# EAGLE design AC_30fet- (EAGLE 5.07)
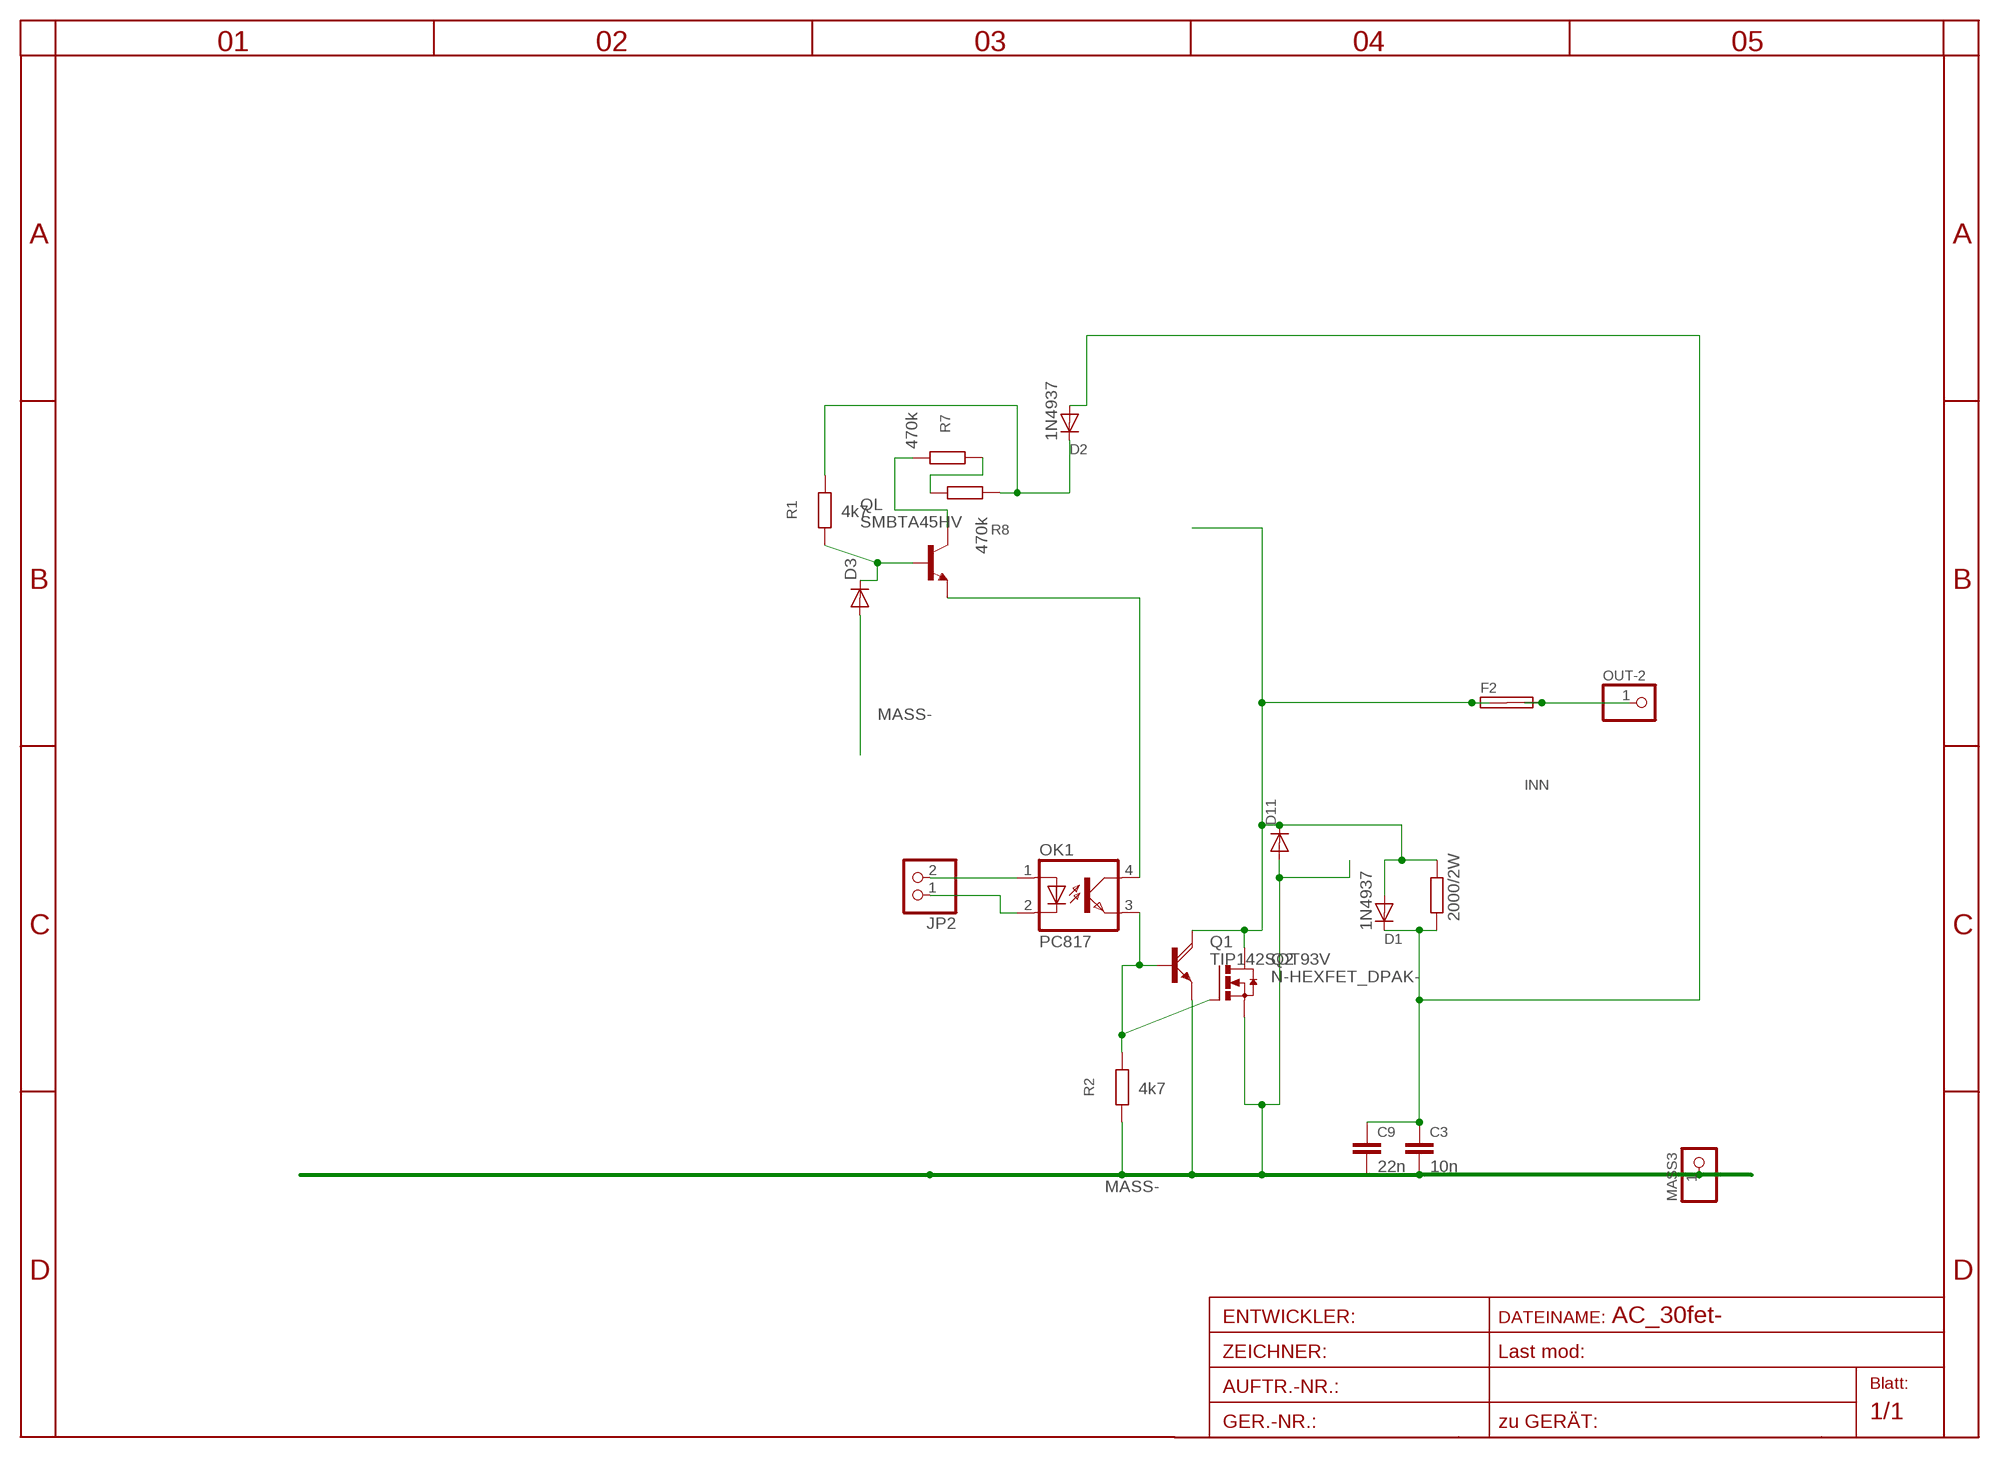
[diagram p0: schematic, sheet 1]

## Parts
C3  10n  C-EU025_050-050X075  [C025_050-050X075]
C9  22n  C-EU150-054X183  [C150-054X183]
D1  1N4937  1N4004DO41-10  [DO41-10]
D2  1N4937  1N400420  [DO41-20]
D3  DIODE-MINIMELF  [MINIMELF]
D11  DIODE-SMC  [SMC]
F2  SHK20L7MM5  [7MM5]
JP2  PINHD-1X2STR  [1X02]
MASS3  PINHD-1X13MM2  [1X3MM2]
OK1  PC817  [DIL04]
OUT-2  PINHD-1X13MM2  [1X3MM2]
Q1  TIP142SOT93V  [SOT93V]
Q2  N-HEXFET_DPAK-  [TO252]
QL  SMBTA45HV  [SOT23HV]
R1  4k7  R-EU_R1206  [R1206]
R2  4k7  R-EU_R1206  [R1206]
R7  470k  R-EU_R1206  [R1206]
R8  470k  R-EU_R1206  [R1206]
R27  2000/2W  R-EU_0207/10  [0207/10]

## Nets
BQL: D3.C QL.1(B) R1.2
D1: D1.A D11.C F2.1A F2.1B Q1.C Q2.3(D) R27.2
INN: F2.2A F2.2B OUT-2.1
MASS-: C3.3 C9.2 D3.A D11.A MASS3.1 Q1.E Q2.2(S) R2.2
N$1: R7.1 R8.2
N$2: C3.1 C9.1 D1.C D2.A R27.1
N$3: JP2.1 OK1.2(C)
N$4: OK1.3(EMIT) Q1.B Q2.1(G) R2.1
N$6: D2.C R1.1 R8.1
N$7: JP2.2 OK1.1(A)
N$9: QL.3(C) R7.2
N$11: OK1.4(COL) QL.2(E)

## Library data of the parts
C3 C9 = rcl-2:C-EU: CAPACITOR, European symbol
D1 D2 = diode:1N4004: DIODE
D3 D11 = diode:DIODE-: DIODE
F2 = fuse:SHK20L: FUSE HOLDER 5 x 20 mm, SH contact, SHH1 Schukat, E1073 Buerklin
JP2 = pinhead:PINHD-1X2: PIN HEADER
MASS3 OUT-2 = pinhead:PINHD-1X1: PIN HEADER
OK1 = optocoupler:PC817: SHARP OPTO COUPLER
Q1 = transistor-power:TIP142: NPN DARLINGTON TRANSISTOR
Q2 = transistor-power:N-HEXFET_?-*: HEXFET® Power MOSFET
QL = transistor-npn:SMBTA45
R1 R2 R7 R8 R27 = rcl-2:R-EU_: RESISTOR, European symbol

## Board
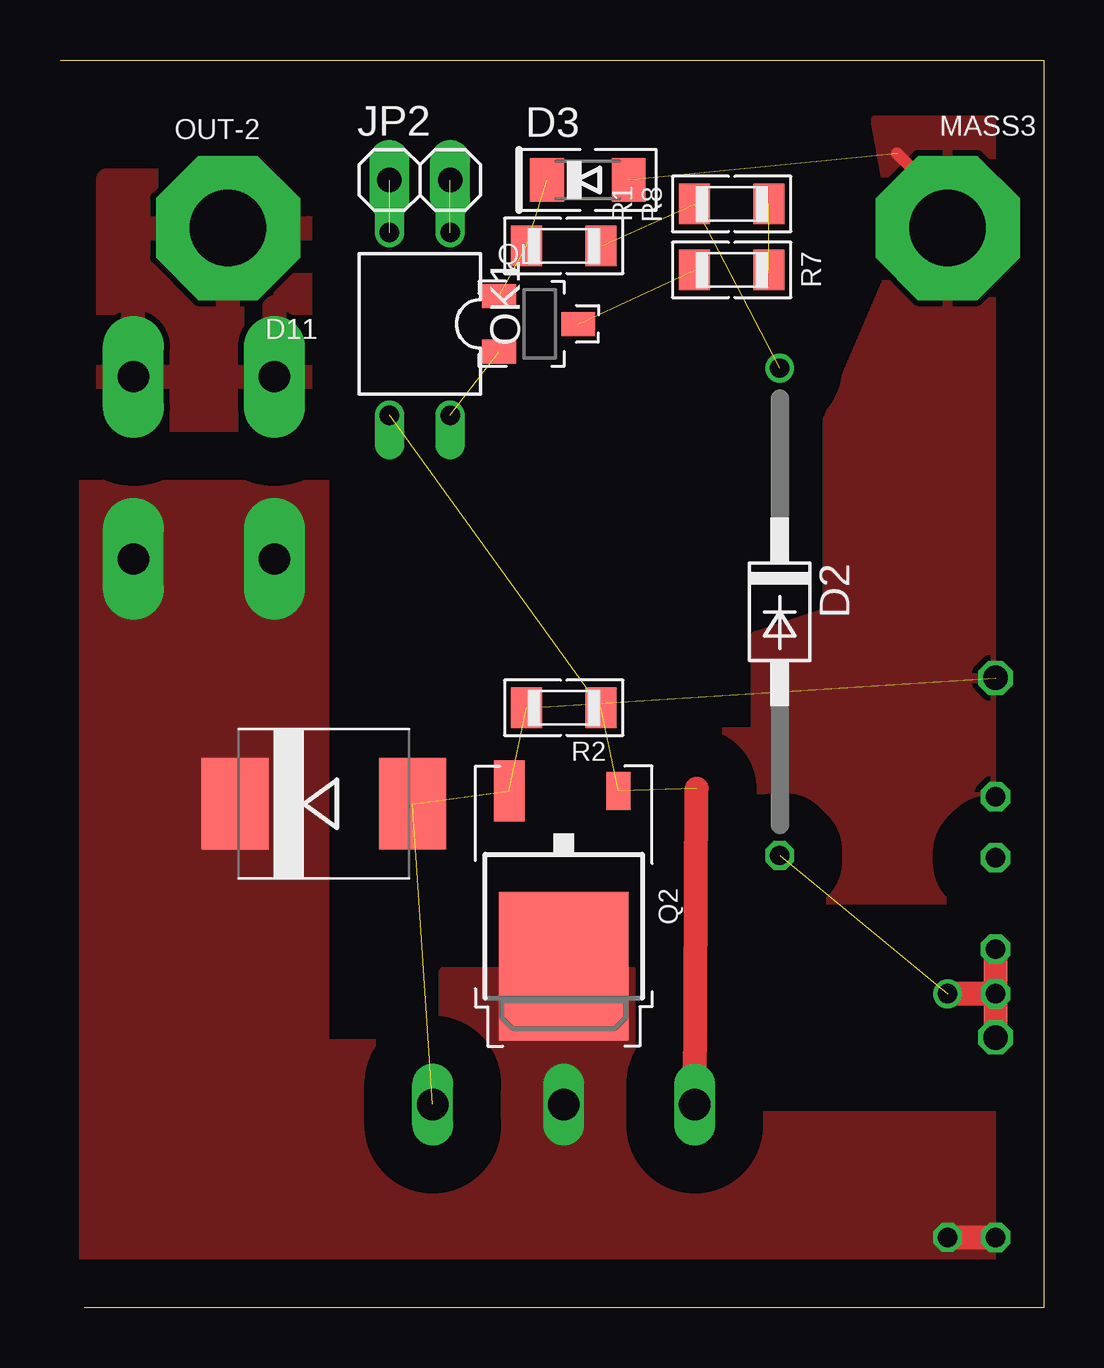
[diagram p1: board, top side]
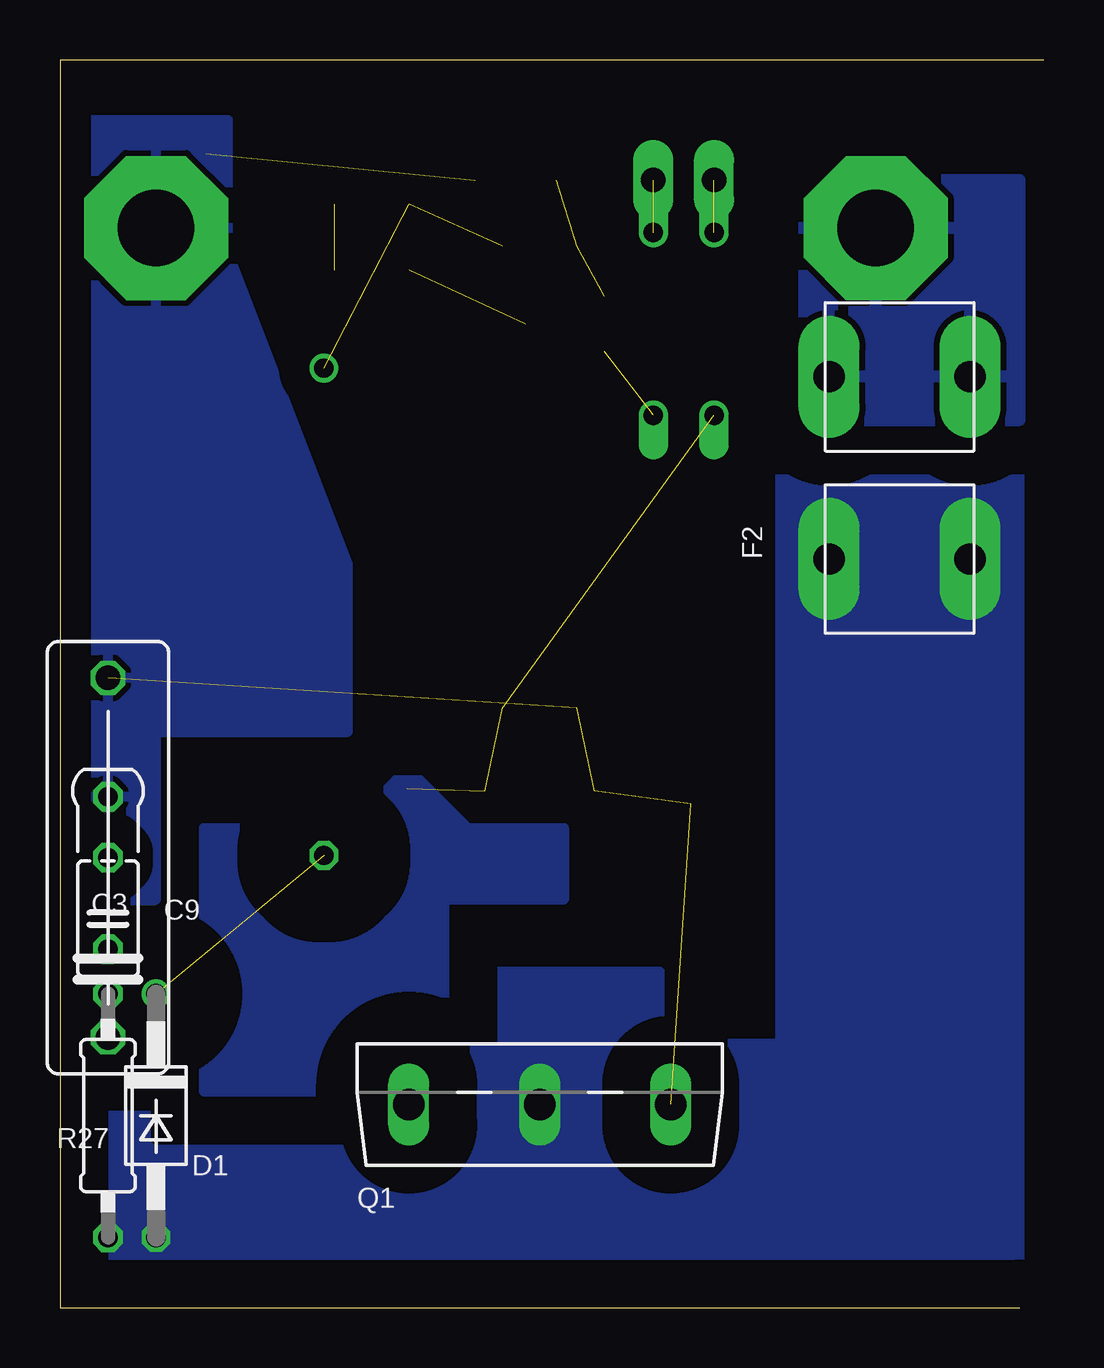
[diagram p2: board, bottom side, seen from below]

Size 41 x 52 mm. Coordinates in mm from the lower left corner, seen from the top.
Outline: 0,52 41,52 41,0 1,0
Copper layers (1*16): Top 0.035mm / dielectric 1.5mm / Bottom 0.035mm
Design rules "default *": minimum track width 12mil, minimum drill 24mil, track to track 8mil, track to pad 8mil, pad to pad 8mil, via to via 8mil, smd to smd 8mil, copper to edge 40mil, drill to drill 8mil, minimum pad ring 8mil, minimum via ring 8mil, stop-mask expansion 4mil, vias tented up to drill 0mil, thermal gap 10mil

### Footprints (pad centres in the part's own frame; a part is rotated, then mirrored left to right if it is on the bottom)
C025_050-050X075 = drill 0.813 octagon: 1 -3.81,0; 2 0,0; 3 2.54,0
C150-054X183 = drill 1.016 octagon: 1 -7.493,0; 2 7.493,0
DO41-10 = drill 0.8 octagon: A 5.08,0 | drill 0.8 round: C -5.08,0
DO41-20 = drill 0.8 octagon: A 10.16,0 | drill 0.8 round: C -10.16,0
MINIMELF = smd 1.4 x 1.8: A 1.7,0; C -1.7,0
SMC = smd 2.8 x 3.8: A 3.7,0; C -3.7,0
7MM5 = drill 1.3 pad 2.54 long: 1A -3.8,2.94; 1B -3.8,-2.94; 2A 3.8,2.94; 2B 3.8,-2.94
1X02 = drill 1.016 pad 1.676 long: 1 -1.27,0; 2 1.27,0
1X3MM2 = drill 3.2 pad 6 octagon: 1 0,0
DIL04 = drill 0.813 offset: 1 -1.27,-3.81; 2 1.27,-3.81; 3 1.27,3.81; 4 -1.27,3.81
SOT93V = drill 1.3 pad 1.676 long: B -5.461,-2.54; C 0,-2.54; E 5.461,-2.54
TO252 = smd 1 x 1.6: 1 -2.28,-3.53 | smd 1.27 x 2.54: 2 2.28,-3.53 | smd 5.4 x 6.2: 3 0,3.77
SOT23HV = smd 1 x 1.4: 1 -1.15,-1.7; 2 1.15,-1.7; 3 0,1.6
R1206 = smd 1.3 x 1.7: 1 -1.55,0; 2 1.55,0
0207/10 = drill 0.813 octagon: 1 -5.08,0; 2 5.08,0

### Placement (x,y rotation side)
C3  39,18.75 90 bottom
C9  39,18.75 90 bottom
D1  37,8 270 bottom
D2  30,29 270 top
D3  22,47 0 top
D11  11,21 0 top
F2  6,35 90 bottom
JP2  15,47 0 top
MASS3  37,45 0 top
OK1  15,41 180 top
OUT-2  7,45 180 top
Q1  21,11 0 bottom
Q2  21,18 180 top
QL  20,41 270 top
R1  21,44.25 180 top
R2  21,25 180 top
R7  28,43.25 180 top
R8  28,46 0 top
R27  39,8 270 bottom

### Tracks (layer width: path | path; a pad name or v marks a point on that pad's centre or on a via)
BQL  (2 unrouted)
D1
  Top 1: D1.A R27.2
  pour Top (isolate 2, rank 2, no thermals): 1,0 1,35 11,35 11,11 16,11 16,14 24,14 24,8 40,8 41,7 41,0
  pour Bottom (isolate 2, rank 2, no thermals): 1,0 1,35 11,35 11,11 16,11 16,14 24,14 24,8 40,8 41,7 41,0
INN
  pour Top: 10,37 2,37 2,47 10,47
  pour Bottom: 10,37 1,37 1,47 10,47
MASS-  (5 unrouted)
  Top 0.5: 34.9,48.1 37,46 MASS3.1
  pour Top (isolate 2, rank 2): 34,49.5 40,49.5 40,17 25,17 25,24 29,24 29,28 32,29 32,37 35,44
  pour Bottom (isolate 1.27, rank 2): 34,49.5 40,49.5 40,17 37,17 37,24 29,24 29,31 34,44
N$1  (1 unrouted)
N$2  (1 unrouted)
  Top 1: D1.C R27.1 C9.1 C3.1
N$3  (1 unrouted)
N$4  (3 unrouted)
  Top 1: Q1.B 26.54,21.63
N$6  (2 unrouted)
N$7  (1 unrouted)
N$9  (1 unrouted)
N$11  (1 unrouted)
SRC1
  pour Bottom (isolate 3): 25,9 35,9 35,20 29,20 27,22 26,22 24,20 20,20 20,17 25,17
